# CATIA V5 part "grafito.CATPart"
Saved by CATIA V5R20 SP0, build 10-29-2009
Part number: grafito
Revision: ANY
Definition: UNKNOWN
Nomenclature: grafito
Source: Unknown
Bounding box of the stored display mesh (mm): x -2.487 to 2.449, y 1.464 to 21.398, z -2.5 to 2.5
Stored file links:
  C:\Users\Utente\Desktop\IO LAVORO\3D X SITO CF\CUMSA\3D files SD\SD 4528\grafito.CATPart
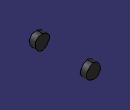
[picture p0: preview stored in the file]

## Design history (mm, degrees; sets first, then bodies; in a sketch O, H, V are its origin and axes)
Body1 "Saliente-Extruir1" (main body)
  Solid1: solid without history
Body2 "Saliente-Extruir1"
  Solid2: solid without history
